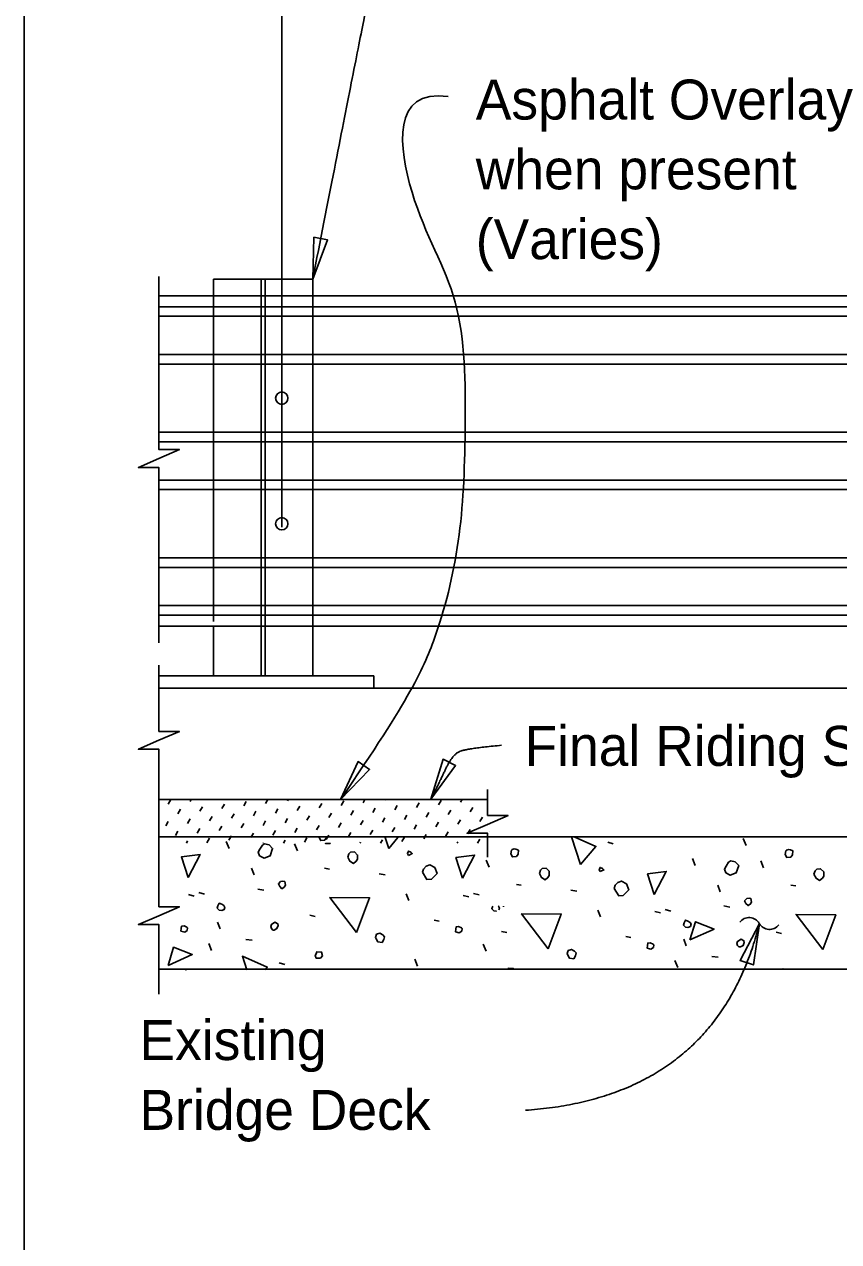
# Model space of a CAD drawing. Extents: x 21526.6 to 21595.9, y 56117 to 56157.3.
# Drawn here: x 21545.72 to 21549.82, y 56132.42 to 56138.56 of the extents above; entities that cross this region are included whole.
import ezdxf

# ---------------------------------------------------------------- set-up
doc = ezdxf.new("R2010")
doc.units = 0
for name, color, linetype in [('AdhocPoint_dp', 7, 'Continuous'), ('Border', 7, 'Continuous'), ('Patterning', 7, 'Continuous'), ('PlotBorder_dp', 7, 'Continuous'), ('SheetBorder_dp', 7, 'Continuous'), ('TextMisc', 7, 'Continuous')]:
    doc.layers.add(name, color=color, linetype=linetype)

msp = doc.modelspace()

# ---------------------------------------------------------------- linework, layer by layer
at = {"layer": 'AdhocPoint_dp'}
for p, q in [((21546.3955, 56135.21), (21554.1792, 56135.21)), ((21548.0534, 56134.6483), (21546.3955, 56134.6483)), ((21554.1792, 56134.46), (21546.3955, 56134.46)), ((21546.3955, 56133.7933), (21554.1792, 56133.7933))]:
    msp.add_line(p, q, dxfattribs=at)
at = {"layer": 'Patterning'}
for p, q in [((21547.0151, 56136.0224), (21547.0151, 56142.7213)), ((21546.4424, 56134.6258), (21546.4553, 56134.6482)), ((21546.553, 56134.6388), (21546.5585, 56134.6483)), ((21546.6018, 56134.59), (21546.6148, 56134.6124)), ((21546.7125, 56134.6029), (21546.7254, 56134.6253)), ((21546.8231, 56134.6159), (21546.8361, 56134.6383)), ((21546.9337, 56134.6289), (21546.945, 56134.6483)), ((21547.0444, 56134.6418), (21547.0481, 56134.6483)), ((21547.0932, 56134.593), (21547.1062, 56134.6154)), ((21547.2038, 56134.6059), (21547.2168, 56134.6283)), ((21547.3145, 56134.6189), (21547.3274, 56134.6413)), ((21547.4251, 56134.6319), (21547.4346, 56134.6483)), ((21547.4739, 56134.583), (21547.4869, 56134.6054)), ((21547.5357, 56134.6448), (21547.5378, 56134.6483)), ((21547.5846, 56134.596), (21547.5975, 56134.6184)), ((21547.6952, 56134.609), (21547.7082, 56134.6314)), ((21547.8058, 56134.6219), (21547.8188, 56134.6443)), ((21547.9165, 56134.6349), (21547.9242, 56134.6483)), ((21547.9653, 56134.5861), (21547.9783, 56134.6084)), ((21548.0271, 56134.6479), (21548.0274, 56134.6483)), ((21546.4912, 56134.577), (21546.5042, 56134.5994)), ((21546.54, 56134.5282), (21546.553, 56134.5506)), ((21546.6507, 56134.5411), (21546.6636, 56134.5635)), ((21546.7613, 56134.5541), (21546.7743, 56134.5765)), ((21546.8719, 56134.5671), (21546.8849, 56134.5894)), ((21546.9826, 56134.58), (21546.9955, 56134.6024)), ((21547.0314, 56134.5312), (21547.0444, 56134.5536)), ((21547.142, 56134.5441), (21547.155, 56134.5665)), ((21547.2527, 56134.5571), (21547.2656, 56134.5795)), ((21547.3633, 56134.5701), (21547.3763, 56134.5925)), ((21547.4121, 56134.5212), (21547.4251, 56134.5436)), ((21547.5228, 56134.5342), (21547.5357, 56134.5566)), ((21547.6334, 56134.5472), (21547.6464, 56134.5696)), ((21547.744, 56134.5601), (21547.757, 56134.5825)), ((21547.8547, 56134.5731), (21547.8676, 56134.5955)), ((21547.9035, 56134.5243), (21547.9165, 56134.5467)), ((21548.0141, 56134.5372), (21548.0271, 56134.5596)), ((21546.4294, 56134.5152), (21546.4424, 56134.5376)), ((21546.4782, 56134.4664), (21546.4912, 56134.4888)), ((21546.5889, 56134.4793), (21546.6018, 56134.5017)), ((21546.6995, 56134.4923), (21546.7125, 56134.5147)), ((21546.8101, 56134.5053), (21546.8231, 56134.5276)), ((21546.9208, 56134.5182), (21546.9337, 56134.5406)), ((21546.9696, 56134.4694), (21546.9826, 56134.4918)), ((21547.0802, 56134.4823), (21547.0932, 56134.5047)), ((21547.1909, 56134.4953), (21547.2038, 56134.5177)), ((21547.3015, 56134.5083), (21547.3145, 56134.5307)), ((21547.3503, 56134.4594), (21547.3633, 56134.4818)), ((21547.461, 56134.4724), (21547.4739, 56134.4948)), ((21547.5716, 56134.4854), (21547.5846, 56134.5078)), ((21547.6822, 56134.4983), (21547.6952, 56134.5207)), ((21547.7929, 56134.5113), (21547.8058, 56134.5337)), ((21547.8417, 56134.4625), (21547.8547, 56134.4849)), ((21547.9523, 56134.4754), (21547.9653, 56134.4978)), ((21548.063, 56134.4884), (21548.0631, 56134.4886)), ((21546.5339, 56134.4293), (21546.54, 56134.4399)), ((21546.6377, 56134.4305), (21546.6507, 56134.4529)), ((21546.7494, 56134.4017), (21546.7352, 56134.4371)), ((21546.7483, 56134.4435), (21546.7613, 56134.4658)), ((21546.859, 56134.4564), (21546.8719, 56134.4788)), ((21546.9204, 56134.4293), (21546.9208, 56134.43)), ((21547.0235, 56134.4293), (21547.0314, 56134.4429)), ((21547.0935, 56134.3899), (21547.0793, 56134.4253)), ((21547.1291, 56134.4335), (21547.142, 56134.4559)), ((21547.2397, 56134.4465), (21547.2527, 56134.4689)), ((21547.41, 56134.4293), (21547.4121, 56134.433)), ((21547.5132, 56134.4293), (21547.5228, 56134.446)), ((21547.6204, 56134.4365), (21547.6334, 56134.4589)), ((21547.7311, 56134.4495), (21547.744, 56134.4719)), ((21547.8996, 56134.4293), (21547.9035, 56134.436)), ((21548.0028, 56134.4293), (21548.0141, 56134.449)), ((21548.659, 56134.4328), (21548.6873, 56134.4258)), ((21549.3573, 56134.4169), (21549.3431, 56134.4523)), ((21546.8749, 56134.2691), (21546.8625, 56134.3027)), ((21547.2313, 56134.3016), (21547.2561, 56134.298)), ((21548.0604, 56134.3079), (21548.0462, 56134.3433)), ((21549.101, 56134.3162), (21549.0868, 56134.3515)), ((21549.4451, 56134.3044), (21549.4309, 56134.3398)), ((21547.5071, 56134.2733), (21547.5372, 56134.268)), ((21546.5973, 56134.179), (21546.6256, 56134.1719)), ((21546.8937, 56134.1973), (21546.9238, 56134.192)), ((21547.982, 56134.1754), (21548.0103, 56134.1684)), ((21548.1983, 56134.2196), (21548.223, 56134.216)), ((21548.474, 56134.1913), (21548.5041, 56134.186)), ((21549.2265, 56134.1836), (21549.2141, 56134.2172)), ((21549.5829, 56134.216), (21549.6077, 56134.2125)), ((21546.5449, 56134.169), (21546.5732, 56134.1619)), ((21547.6556, 56134.1389), (21547.6432, 56134.1725)), ((21547.9296, 56134.1654), (21547.9579, 56134.1584)), ((21547.1571, 56134.0647), (21547.1836, 56134.0594)), ((21548.6225, 56134.0569), (21548.6102, 56134.0905)), ((21548.8965, 56134.0834), (21548.9248, 56134.0764)), ((21548.9489, 56134.0934), (21548.9772, 56134.0864)), ((21549.2453, 56134.1117), (21549.2753, 56134.1064)), ((21546.7034, 56133.9964), (21546.691, 56134.0299)), ((21547.7829, 56134.0399), (21547.8094, 56134.0346)), ((21546.8336, 56133.9427), (21546.8654, 56133.9392)), ((21548.124, 56133.9827), (21548.1505, 56133.9774)), ((21548.7498, 56133.9579), (21548.7763, 56133.9526)), ((21549.055, 56133.9108), (21549.0426, 56133.9444)), ((21549.5087, 56133.9791), (21549.5352, 56133.9738)), ((21546.661, 56133.8868), (21546.6468, 56133.9221)), ((21548.0457, 56133.8832), (21548.0315, 56133.9186)), ((21547.0015, 56133.8243), (21547.0298, 56133.8172)), ((21547.6998, 56133.8084), (21547.6857, 56133.8437)), ((21549.0126, 56133.8012), (21548.9984, 56133.8366)), ((21549.1852, 56133.8572), (21549.217, 56133.8536))]:
    msp.add_line(p, q, dxfattribs=at)
for points in [[(21546.9032, 56134.3646), (21546.9261, 56134.3522), (21546.9562, 56134.3646), (21546.9686, 56134.4017), (21546.9509, 56134.4194), (21546.9279, 56134.4247), (21546.9173, 56134.4176), (21546.9049, 56134.3982), (21546.8961, 56134.3823), (21546.9032, 56134.3646)], [(21547.2033, 56134.4566), (21547.2119, 56134.4412), (21547.2313, 56134.443), (21547.2402, 56134.4554), (21547.2403, 56134.4566)], [(21547.2354, 56134.4293), (21547.2364, 56134.4269), (21547.234, 56134.4293)], [(21547.2364, 56134.4269), (21547.2576, 56134.4269), (21547.2601, 56134.4293)], [(21547.5548, 56134.4023), (21547.5372, 56134.4566)], [(21547.6008, 56134.4566), (21547.5548, 56134.4023)], [(21548.5218, 56134.3203), (21548.4763, 56134.46)], [(21548.4902, 56134.46), (21548.5995, 56134.4122), (21548.5218, 56134.3203)], [(21546.5425, 56134.255), (21546.509, 56134.3593), (21546.6026, 56134.3716), (21546.5425, 56134.255)], [(21547.348, 56134.3581), (21547.3586, 56134.3369), (21547.3763, 56134.3263), (21547.3904, 56134.3369), (21547.3975, 56134.3475), (21547.3975, 56134.3687), (21547.3816, 56134.3846), (21547.3622, 56134.3829), (21547.3533, 56134.374), (21547.348, 56134.3581)], [(21547.6538, 56134.367), (21547.6733, 56134.3758), (21547.6662, 56134.3829), (21547.6538, 56134.3882), (21547.6485, 56134.3758), (21547.6538, 56134.367)], [(21547.9272, 56134.2514), (21547.8936, 56134.3557), (21547.9873, 56134.3681), (21547.9272, 56134.2514)], [(21548.17, 56134.3751), (21548.1788, 56134.3592), (21548.1983, 56134.361), (21548.2071, 56134.3734), (21548.2089, 56134.3928), (21548.1965, 56134.3981), (21548.1877, 56134.3999), (21548.177, 56134.3963), (21548.1735, 56134.3928), (21548.17, 56134.3751)], [(21549.5547, 56134.3716), (21549.5635, 56134.3557), (21549.5829, 56134.3574), (21549.5918, 56134.3698), (21549.5935, 56134.3893), (21549.5812, 56134.3946), (21549.5723, 56134.3963), (21549.5617, 56134.3928), (21549.5582, 56134.3893), (21549.5547, 56134.3716)], [(21547.7245, 56134.2821), (21547.7475, 56134.245), (21547.7705, 56134.2468), (21547.7793, 56134.2556), (21547.7988, 56134.275), (21547.7864, 56134.3051), (21547.7617, 56134.3192), (21547.744, 56134.3122), (21547.7299, 56134.298), (21547.7245, 56134.2821)], [(21548.3149, 56134.2761), (21548.3255, 56134.2549), (21548.3432, 56134.2443), (21548.3574, 56134.2549), (21548.3644, 56134.2655), (21548.3644, 56134.2867), (21548.3485, 56134.3026), (21548.3291, 56134.3009), (21548.3202, 56134.292), (21548.3149, 56134.2761)], [(21548.6208, 56134.285), (21548.6402, 56134.2938), (21548.6331, 56134.3009), (21548.6208, 56134.3062), (21548.6155, 56134.2938), (21548.6208, 56134.285)], [(21549.2548, 56134.279), (21549.2777, 56134.2667), (21549.3078, 56134.279), (21549.3202, 56134.3162), (21549.3025, 56134.3338), (21549.2795, 56134.3391), (21549.2689, 56134.3321), (21549.2565, 56134.3126), (21549.2477, 56134.2967), (21549.2548, 56134.279)], [(21549.6996, 56134.2726), (21549.7102, 56134.2514), (21549.7279, 56134.2408), (21549.742, 56134.2514), (21549.7491, 56134.262), (21549.7491, 56134.2832), (21549.7332, 56134.2991), (21549.7138, 56134.2973), (21549.7049, 56134.2885), (21549.6996, 56134.2726)], [(21547.0051, 56134.2096), (21547.0157, 56134.199), (21547.0263, 56134.2061), (21547.0334, 56134.2167), (21547.0298, 56134.2344), (21547.021, 56134.2362), (21547.0086, 56134.2344), (21546.998, 56134.2238), (21547.0051, 56134.2096)], [(21548.6915, 56134.2001), (21548.7145, 56134.163), (21548.7374, 56134.1648), (21548.7463, 56134.1736), (21548.7657, 56134.193), (21548.7533, 56134.2231), (21548.7286, 56134.2372), (21548.7109, 56134.2302), (21548.6968, 56134.216), (21548.6915, 56134.2001)], [(21548.8941, 56134.1694), (21548.8605, 56134.2737), (21548.9542, 56134.2861), (21548.8941, 56134.1694)], [(21546.6999, 56134.0906), (21546.7122, 56134.0888), (21546.7246, 56134.0941), (21546.7282, 56134.1047), (21546.7229, 56134.1136), (21546.7122, 56134.1206), (21546.6999, 56134.1259), (21546.6928, 56134.1118), (21546.6893, 56134.1012), (21546.6999, 56134.0906)], [(21547.3922, 56133.9781), (21547.2579, 56134.1548), (21547.4576, 56134.1531), (21547.3922, 56133.9781)], [(21549.3567, 56134.1241), (21549.3673, 56134.1135), (21549.3779, 56134.1206), (21549.3849, 56134.1312), (21549.3814, 56134.1488), (21549.3726, 56134.1506), (21549.3602, 56134.1488), (21549.3496, 56134.1382), (21549.3567, 56134.1241)], [(21548.0789, 56134.1111), (21548.0775, 56134.1082), (21548.0739, 56134.0976), (21548.0845, 56134.087)], [(21548.0845, 56134.087), (21548.0969, 56134.0853), (21548.0988, 56134.0861)], [(21548.1101, 56134.0931), (21548.1128, 56134.1012), (21548.1075, 56134.11), (21548.1059, 56134.1111)], [(21548.133, 56134.1072), (21548.1342, 56134.1111)], [(21548.3591, 56133.8961), (21548.2248, 56134.0728), (21548.4245, 56134.0711), (21548.3591, 56133.8961)], [(21549.7438, 56133.8925), (21549.6095, 56134.0693), (21549.8092, 56134.0675), (21549.7438, 56133.8925)], [(21546.506, 56133.9851), (21546.5255, 56133.9798), (21546.5379, 56133.9887), (21546.5396, 56134.001), (21546.5361, 56134.0046), (21546.522, 56134.0116), (21546.5096, 56134.0099), (21546.5078, 56133.9975), (21546.506, 56133.9851)], [(21546.9697, 56133.9904), (21546.9768, 56133.9904), (21546.9909, 56133.9975), (21546.9962, 56134.0134), (21546.9945, 56134.0223), (21546.9803, 56134.0293), (21546.9626, 56134.0187), (21546.9591, 56134.0081), (21546.9626, 56133.9975), (21546.9697, 56133.9904)], [(21547.8907, 56133.9816), (21547.9102, 56133.9763), (21547.9225, 56133.9851), (21547.9243, 56133.9975), (21547.9208, 56134.001), (21547.9066, 56134.0081), (21547.8943, 56134.0063), (21547.8925, 56133.994), (21547.8907, 56133.9816)], [(21549.0515, 56134.005), (21549.0638, 56134.0033), (21549.0762, 56134.0086), (21549.0798, 56134.0192), (21549.0744, 56134.028), (21549.0638, 56134.0351), (21549.0515, 56134.0404), (21549.0444, 56134.0262), (21549.0409, 56134.0156), (21549.0515, 56134.005)], [(21549.0738, 56133.9403), (21549.1021, 56134.0322), (21549.1958, 56133.9951), (21549.0738, 56133.9403)], [(21547.4912, 56133.9462), (21547.5, 56133.9303), (21547.5213, 56133.9268), (21547.5301, 56133.9427), (21547.5336, 56133.9568), (21547.5248, 56133.9657), (21547.5089, 56133.9745), (21547.493, 56133.9692), (21547.4877, 56133.9533), (21547.4912, 56133.9462)], [(21549.3213, 56133.9049), (21549.3284, 56133.9049), (21549.3425, 56133.912), (21549.3478, 56133.9279), (21549.3461, 56133.9367), (21549.3319, 56133.9438), (21549.3142, 56133.9332), (21549.3107, 56133.9226), (21549.3142, 56133.912), (21549.3213, 56133.9049)], [(21546.4412, 56133.8116), (21546.4695, 56133.9035), (21546.5632, 56133.8664), (21546.4412, 56133.8116)], [(21547.1889, 56133.849), (21547.2101, 56133.849), (21547.2207, 56133.8596), (21547.2154, 56133.8791), (21547.1925, 56133.8808), (21547.1889, 56133.8702), (21547.1836, 56133.8614), (21547.1889, 56133.849), (21547.1854, 56133.8525)], [(21548.4581, 56133.8642), (21548.467, 56133.8483), (21548.4882, 56133.8448), (21548.497, 56133.8607), (21548.5006, 56133.8748), (21548.4917, 56133.8837), (21548.4758, 56133.8925), (21548.4599, 56133.8872), (21548.4546, 56133.8713), (21548.4581, 56133.8642)], [(21548.8576, 56133.8996), (21548.8771, 56133.8943), (21548.8895, 56133.9031), (21548.8912, 56133.9155), (21548.8877, 56133.919), (21548.8735, 56133.9261), (21548.8612, 56133.9243), (21548.8594, 56133.912), (21548.8576, 56133.8996)], [(21546.8388, 56133.79), (21546.8165, 56133.8585), (21546.9421, 56133.8037), (21546.9305, 56133.79)], [(21546.5368, 56133.79), (21546.5302, 56133.7913), (21546.5262, 56133.79)], [(21548.1834, 56133.7933), (21548.1824, 56133.7971), (21548.1594, 56133.7988), (21548.1575, 56133.7933)], [(21549.5671, 56133.7933), (21549.567, 56133.7935), (21549.544, 56133.7953), (21549.5434, 56133.7933)]]:
    msp.add_lwpolyline(points, dxfattribs=at)
at = {"layer": 'PlotBorder_dp'}
msp.add_line((21545.7163, 56153.2556), (21545.7163, 56127.3172), dxfattribs=at)
for points in [[(21547.1713, 56137.2726), (21547.2461, 56137.4701), (21547.1768, 56137.4837)], [(21547.7672, 56134.6496), (21547.8919, 56134.8201), (21547.8288, 56134.8517)], [(21547.3105, 56134.6482), (21547.4577, 56134.7997), (21547.3996, 56134.8397)], [(21549.4247, 56134.0233), (21549.3942, 56133.8143), (21549.3271, 56133.836)]]:
    msp.add_lwpolyline(points, close=True, dxfattribs=at)
for points in [[(21546.3955, 56135.4395), (21546.3955, 56136.3228), (21546.2921, 56136.3228), (21546.3955, 56136.3678), (21546.4988, 56136.4128), (21546.3955, 56136.4128), (21546.3955, 56137.2857)], [(21546.3955, 56134.4321), (21546.3955, 56134.9022), (21546.2921, 56134.9022), (21546.3955, 56134.9472), (21546.4988, 56134.9922), (21546.3955, 56134.9922), (21546.3955, 56135.3267)], [(21548.0534, 56134.3575), (21548.0534, 56134.4784), (21547.9501, 56134.4784), (21548.0534, 56134.5234), (21548.1568, 56134.5684), (21548.0534, 56134.5684), (21548.0534, 56134.699)], [(21546.3955, 56133.667), (21546.3955, 56134.0177), (21546.2921, 56134.0177), (21546.3955, 56134.0627), (21546.4988, 56134.1077), (21546.3955, 56134.1077), (21546.3955, 56134.4321)]]:
    msp.add_lwpolyline(points, dxfattribs=at)
for centre, start, end in [((21549.3723, 56133.9936), 30.00813, 141.73535), ((21549.4755, 56134.0532), 210.00813, 321.73535)]:
    msp.add_arc(centre, 0.0596, start, end, dxfattribs=at)
for points, degree in [([(21547.7365, 56139.0917), (21547.573, 56139.0917), (21547.5207, 56139.0394), (21547.4226, 56138.552), (21547.1713, 56137.2726)], 2), ([(21547.8542, 56138.1934), (21547.5677, 56138.2343), (21547.6407, 56137.6336), (21547.9384, 56137.195), (21547.9442, 56136.5212), (21547.927, 56135.9787), (21547.8072, 56135.4705), (21547.6617, 56135.1578), (21547.3105, 56134.6481)], 3), ([(21548.1235, 56134.922), (21547.9499, 56134.9066), (21547.8757, 56134.8752), (21547.8101, 56134.7353), (21547.7672, 56134.6496)], 2), ([(21549.4247, 56134.0233), (21549.2041, 56133.1495), (21548.2449, 56133.0813)], 2)]:
    msp.add_open_spline(points, degree=degree, dxfattribs=at)
at = {"layer": 'SheetBorder_dp'}
for p, q in [((21546.9109, 56135.2726), (21546.9109, 56137.2726)), ((21546.9317, 56135.2726), (21546.9317, 56137.2726)), ((21546.6713, 56137.1892), (21546.6713, 56135.5456)), ((21547.1713, 56137.1892), (21547.1713, 56135.5225))]:
    msp.add_line(p, q, dxfattribs=at)
at = {"layer": 'TextMisc'}
for p, q in [((21547.1713, 56137.2726), (21546.6713, 56137.2726)), ((21546.6713, 56137.2726), (21546.6713, 56137.1892)), ((21547.1713, 56137.2726), (21547.1713, 56137.1892)), ((21552.8484, 56137.1892), (21546.3955, 56137.1892)), ((21546.3955, 56137.1336), (21552.8484, 56137.1336)), ((21546.3955, 56137.0854), (21552.8484, 56137.0854)), ((21546.3955, 56136.8926), (21552.8484, 56136.8926)), ((21546.3955, 56136.8444), (21552.8484, 56136.8444)), ((21546.3955, 56136.5004), (21552.8484, 56136.5004)), ((21546.3955, 56136.4522), (21552.8484, 56136.4522)), ((21546.3955, 56136.2594), (21552.8484, 56136.2594)), ((21546.3955, 56136.2112), (21552.8484, 56136.2112)), ((21546.3955, 56135.8673), (21552.8484, 56135.8673)), ((21546.3955, 56135.8191), (21552.8484, 56135.8191)), ((21546.3955, 56135.6262), (21552.8484, 56135.6262)), ((21546.3955, 56135.578), (21552.8484, 56135.578)), ((21552.8484, 56135.5225), (21546.3955, 56135.5225)), ((21546.6713, 56135.5225), (21546.6713, 56135.2726)), ((21547.1713, 56135.5225), (21547.1713, 56135.2726)), ((21547.4788, 56135.2726), (21546.3955, 56135.2726)), ((21547.1713, 56135.2726), (21546.6713, 56135.2726)), ((21547.4788, 56135.2726), (21547.4788, 56135.2101)), ((21547.4788, 56135.2101), (21546.3955, 56135.2101))]:
    msp.add_line(p, q, dxfattribs=at)
for centre in [(21547.0151, 56136.6725), (21547.0151, 56136.0393)]:
    msp.add_circle(centre, 0.0312, dxfattribs=at)

# ---------------------------------------------------------------- texts
at = {"layer": 'Border'}
msp.add_text('Final Riding Surface', height=0.2016, dxfattribs=at).set_placement((21548.2396, 56134.8183))
at = {"layer": 'PlotBorder_dp'}
for s, p in [('Asphalt Overlay', (21547.9936, 56138.0774)), ('when present', (21547.9936, 56137.7254)), ('(Varies)', (21547.9936, 56137.3734)), ('Existing ', (21546.2971, 56133.3348)), ('Bridge Deck', (21546.2971, 56132.9828))]:
    msp.add_text(s, height=0.2016, dxfattribs=at).set_placement(p)

doc.saveas('drawing.dxf')
